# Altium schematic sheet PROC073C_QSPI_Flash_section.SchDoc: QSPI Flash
size 431 x 279 mm; Date: Not shown in title block; ApprovedBy: Not shown in title block; CheckedBy: Not shown in title block; Author: Not shown in title block; CompanyName: Not shown in title block; DrawnBy: Charles F. Oladimeji; Engineer: Not shown in title block; Organization: Not shown in title block; Address1: Not shown in title block; Address2: Not shown in title block; Address3: Not shown in title block; Address4: Not shown in title block; DocumentNumber: 6; Revision: Use project parameter SCH_Rev; SheetNumber: 6; SheetTotal: 13; PageSetup: Record=PageOptions¦CenterHorizontal=True¦CenterVertical=True¦PrintScale=1.00¦XCorrection=1.00¦YCorrection=1.00¦PrintKind=0¦BorderSize=5000000¦LeftOffset=0¦BottomOffset=0¦Orientation=2¦PaperLength=1000¦PaperWidth=1000¦Scale=100¦PaperSource=15¦PrintQuality=600¦MediaType=1¦DitherType=10¦PaperKind=Letter¦PrintScaleMode=1
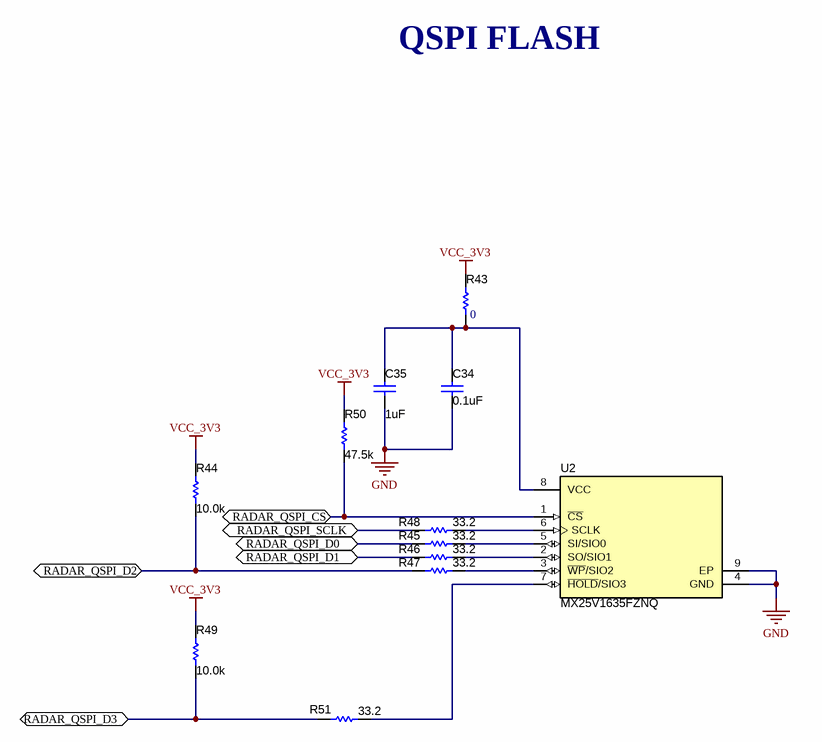
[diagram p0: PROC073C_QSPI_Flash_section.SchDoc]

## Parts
C34  ValueDisplayed: 0.1uF  [0402L]  (hidden comment: CGA2B3X7R1H104K050BB)
C35  ValueDisplayed: 1uF  [0603]  (hidden comment: GCM188R71C105KA64D)
R43  ValueDisplayed: 0  [0402]  (hidden comment: ERJ-2GE0R00X)
R44  ValueDisplayed: 10.0k  [0402L]  (hidden comment: CRCW040210K0FKED)
R45  ValueDisplayed: 33.2  [0201_Silk]  (hidden comment: CRCW020133R2FNED)
R46  ValueDisplayed: 33.2  [0201_Silk]  (hidden comment: CRCW020133R2FNED)
R47  ValueDisplayed: 33.2  [0201_Silk]  (hidden comment: CRCW020133R2FNED)
R48  ValueDisplayed: 33.2  [0201_Silk]  (hidden comment: CRCW020133R2FNED)
R49  ValueDisplayed: 10.0k  [0402L]  (hidden comment: CRCW040210K0FKED)
R50  ValueDisplayed: 47.5k  [0402L]  (hidden comment: CRCW040247K5FKED)
R51  ValueDisplayed: 33.2  [0201_Silk]  (hidden comment: CRCW020133R2FNED)
U2  MX25V1635FZNQ  [WSON-8L_6x5MM_EP]

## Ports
RADAR_QSPI_CS (bidir), RADAR_QSPI_D0 (bidir), RADAR_QSPI_D1 (bidir), RADAR_QSPI_D2 (bidir), RADAR_QSPI_D3 (bidir), RADAR_QSPI_SCLK (bidir)

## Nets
GND: C34.1 C35.1 U2.4(GND) U2.9(EP)
VCC_3V3: R43.2 R44.2 R49.2 R50.1
RADAR_QSPI_CS: R50.2 U2.1(~{CS}) ; port RADAR_QSPI_CS
RADAR_QSPI_D0: R45.2 ; port RADAR_QSPI_D0
RADAR_QSPI_D1: R46.1 ; port RADAR_QSPI_D1
RADAR_QSPI_D2: R44.1 R47.1 ; port RADAR_QSPI_D2
RADAR_QSPI_D3: R49.1 R51.2 ; port RADAR_QSPI_D3
RADAR_QSPI_SCLK: R48.2 ; port RADAR_QSPI_SCLK
NetC34_2: C34.2 C35.2 R43.1 U2.8(VCC)
NetR45_1: R45.1 U2.5(SI/SIO0)
NetR46_2: R46.2 U2.2(SO/SIO1)
NetR47_2: R47.2 U2.3(~{WP}/SIO2)
NetR48_1: R48.1 U2.6(SCLK)
NetR51_1: R51.1 U2.7(~{HOLD}/SIO3)

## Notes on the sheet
- QSPI FLASH

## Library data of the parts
C34 = CMP-0006325-2: CAP, CERM, 0.1 uF, 50 V, +/- 10%, X7R, AEC-Q200 Grade 1, 0402; Manufacturer: TDK; TaMin_C: -55°C; ESR_ohm: 0.039064; Polarized: N; SizeAreaWB_mm2: 3; Value1: 0.039064 ohm; U/M: EA; Value: 0.1uF; TaMax_C: 125°C; SizeZ_mm: 0.6; SizeX_mm: 1; SizeY_mm: 0.5; Cap_Case: 0402; Value2: 50V; AEC Qualified: Y; Cap_F: 100nF; IRMS_A: 8.14669dA; AEC Category: Q200
C35 = CMP-0007136-5: CAP, CERM, 1 uF, 16 V, +/- 10%, X7R, AEC-Q200 Grade 1, 0603; Manufacturer: MuRata; TaMin_C: -55°C; Polarized: N; SizeAreaWB_mm2: 4.68; Value1: Unknown; U/M: EA; Value: 1uF; TaMax_C: 125°C; SizeZ_mm: 1; SizeX_mm: 1.6; SizeY_mm: 0.8; Value2: 16V; SizeArea_mm2: 1.28; CompType: Capacitor; AEC Qualified: Y; Cap_F: 1µF; AEC Category: Q200
R43 = CMP-0026992-3: RES, 0, 5%, 0.1 W, AEC-Q200 Grade 0, 0402; Manufacturer: Panasonic; Power_W: 100mW; TempCo: 600 ppm/C; Value_Code: 0000; Value: 0; EIA_Code: E24; SizeX_mm: 1; SizeY_mm: 0.5; SizeZ_mm: 0.6; Value2: 0.1W; AEC Qualified: Y; VDC_V: 50V; AEC Category: Q200; SizeAreaWB_mm2: 3
R44 R49 = CMP-0025958-3: RES, 10.0 k, 1%, 0.063 W, AEC-Q200 Grade 0, 0402; Manufacturer: Vishay-Dale; Power_W: 63mW; TempCo: 100 ppm/C; Value_Code: 10k0; Value: 10.0k; EIA_Code: E96; Res_ohm: 10k; SizeX_mm: 1; SizeY_mm: 0.5; SizeZ_mm: 0.6; Value2: 0.063W; AEC Qualified: Y; VDC_V: 50V; AEC Category: Q200; AEC Grade: 0
R45-R48 R51 = CMP-0027275-3: RES, 33.2, 1%, 0.05 W, 0201; Manufacturer: Vishay-Dale; Power_W: 50mW; TempCo: 200 ppm/C; Value_Code: 33R2; Value: 33.2; EIA_Code: E96; SizeX_mm: 0.6; SizeY_mm: 0.3; SizeZ_mm: 0.26; Value2: 0.05W; SizeArea_mm2: 0.18; AEC Qualified: N; AEC Category: Q200
R50 = CMP-0026395-2: RES, 47.5 k, 1%, 0.063 W, AEC-Q200 Grade 0, 0402; Manufacturer: Vishay-Dale; Power_W: 63mW; TempCo: 100 ppm/C; Value_Code: 47k5; Value: 47.5k; EIA_Code: E96; SizeX_mm: 1; SizeY_mm: 0.5; SizeZ_mm: 0.6; Value2: 0.063W; AEC Qualified: Y; VDC_V: 50V; AEC Category: Q200; AEC Grade: 0
U2 = CMP-0079267-1: 2.3V-3.6V, 16M-BIT [x 1/x 2/x 4] CMOS FLASH Memory, WSON-8; Manufacturer: Macronix International Co., LTD; SizeArea_mm2: 30; SizeAreaWB_mm2: 56; SizeY_mm: 5; SizeZ_mm: 0.8; SizeX_mm: 6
